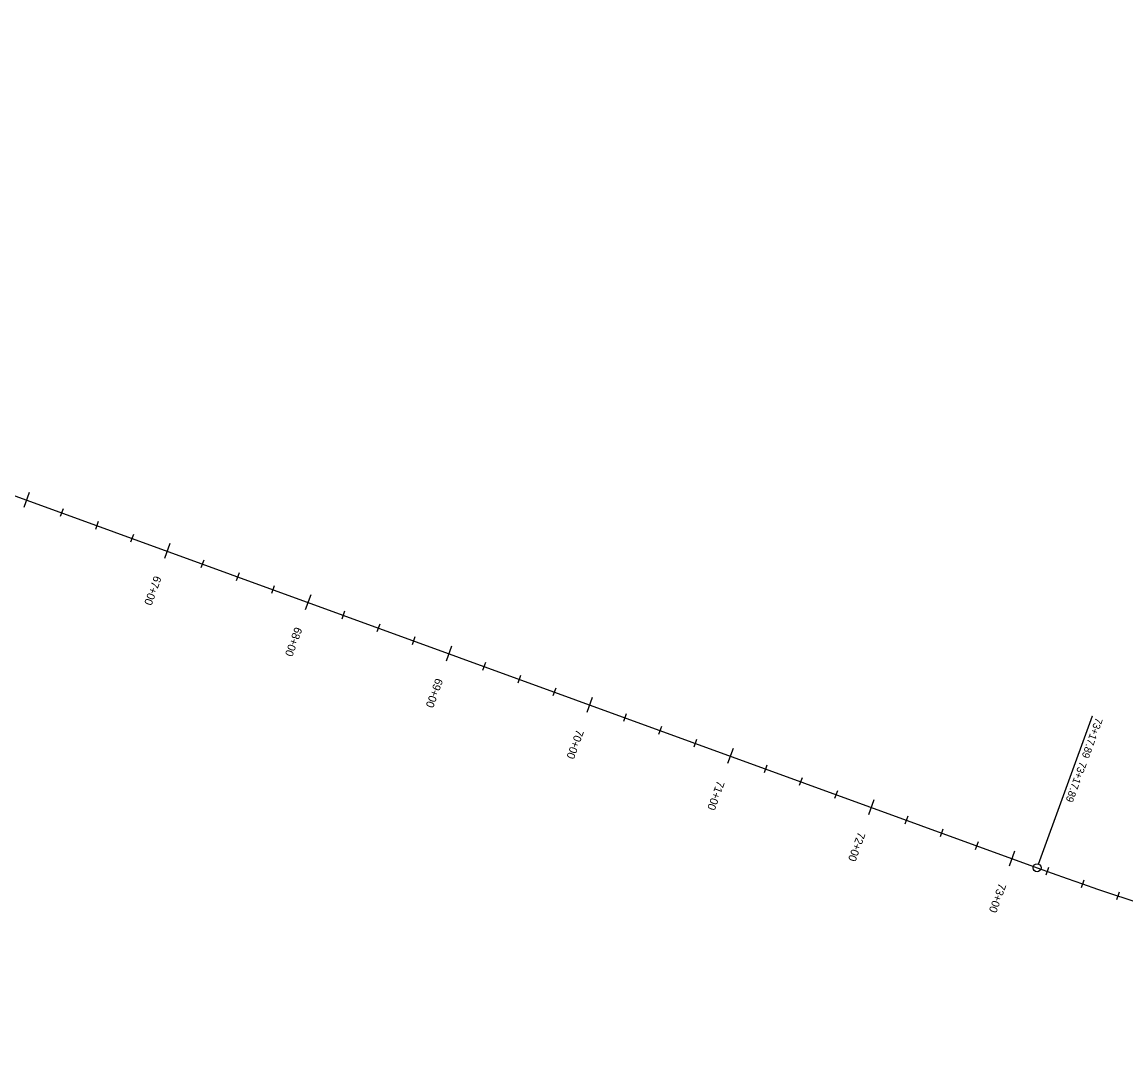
# Model space of a CAD drawing. Extents: x 2301963 to 2307911, y 760768 to 761974.
# Drawn here: x 2303447 to 2304184, y 760898 to 761590 of the extents above; entities that cross this region are included whole.
import ezdxf

# ---------------------------------------------------------------- set-up
doc = ezdxf.new("R2010")
doc.units = 0
for name, color, linetype in [('Default', 7, 'Continuous'), ('Draft_Station Cardinal Lines', 7, 'Continuous'), ('Draft_Station Cardinal Points', 7, 'Continuous'), ('Draft_Station Labels Major', 7, 'Continuous'), ('Draft_Station Ticks Major', 7, 'Continuous'), ('Draft_Station Ticks Minor', 7, 'Continuous'), ('Geom_Secondary', 7, 'Continuous')]:
    doc.layers.add(name, color=color, linetype=linetype)

msp = doc.modelspace()

# ---------------------------------------------------------------- linework, layer by layer
at = {"layer": 'Default'}
msp.add_line((2302574.09, 761590.06), (2304124.97, 761025.72), dxfattribs=at)
msp.add_arc((2304853.32, 763027.32), 2130, 250.00439, 268.36584, dxfattribs=at)
at = {"layer": 'Draft_Station Cardinal Lines'}
msp.add_line((2304125.88, 761028.23), (2304161.9, 761127.21), dxfattribs=at)
at = {"layer": 'Draft_Station Cardinal Points'}
for p, q in [((2304161.9, 761127.21), (2304161.9, 761127.21)), ((2304124.97, 761025.72), (2304124.97, 761025.72))]:
    msp.add_line(p, q, dxfattribs=at)
msp.add_circle((2304124.97, 761025.72), 2.67, dxfattribs=at)
at = {"layer": 'Draft_Station Ticks Major'}
for p, q in [((2303452.18, 761276.22), (2303448.55, 761266.24)), ((2303546.16, 761242.03), (2303542.52, 761232.05)), ((2303640.13, 761207.83), (2303636.5, 761197.85)), ((2303734.1, 761173.64), (2303730.47, 761163.66)), ((2303828.07, 761139.44), (2303824.44, 761129.46)), ((2303922.04, 761105.25), (2303918.41, 761095.27)), ((2304016.01, 761071.05), (2304012.38, 761061.07)), ((2304109.99, 761036.86), (2304106.36, 761026.88))]:
    msp.add_line(p, q, dxfattribs=at)
at = {"layer": 'Draft_Station Ticks Minor'}
for p, q in [((2303474.79, 761265.25), (2303472.91, 761260.06)), ((2303498.29, 761256.7), (2303496.4, 761251.51)), ((2303521.78, 761248.15), (2303519.89, 761242.96)), ((2303568.77, 761231.05), (2303566.88, 761225.87)), ((2303592.26, 761222.51), (2303590.37, 761217.32)), ((2303615.75, 761213.96), (2303613.86, 761208.77)), ((2303662.74, 761196.86), (2303660.85, 761191.67)), ((2303686.23, 761188.31), (2303684.34, 761183.12)), ((2303709.72, 761179.76), (2303707.84, 761174.57)), ((2303756.71, 761162.66), (2303754.82, 761157.48)), ((2303780.2, 761154.12), (2303778.32, 761148.93)), ((2303803.7, 761145.57), (2303801.81, 761140.38)), ((2303850.68, 761128.47), (2303848.79, 761123.28)), ((2303874.17, 761119.92), (2303872.29, 761114.73)), ((2303897.67, 761111.37), (2303895.78, 761106.18)), ((2303944.65, 761094.27), (2303942.77, 761089.09)), ((2303968.15, 761085.73), (2303966.26, 761080.54)), ((2303991.64, 761077.18), (2303989.75, 761071.99)), ((2304038.63, 761060.08), (2304036.74, 761054.89)), ((2304062.12, 761051.53), (2304060.23, 761046.34)), ((2304085.61, 761042.98), (2304083.72, 761037.8)), ((2304132.59, 761025.9), (2304130.72, 761020.71)), ((2304156.13, 761017.58), (2304154.32, 761012.36)), ((2304179.77, 761009.53), (2304178.02, 761004.3))]:
    msp.add_line(p, q, dxfattribs=at)
at = {"layer": 'Geom_Secondary'}
msp.add_line((2302574.09, 761590.06), (2304124.97, 761025.72), dxfattribs=at)
msp.add_arc((2304853.32, 763027.32), 2130, 250.00439, 268.36584, dxfattribs=at)

# ---------------------------------------------------------------- texts
at = {"layer": 'Draft_Station Cardinal Points'}
for p in [(2304164.24, 761126.36), (2304153.55, 761096.99)]:
    msp.add_text('73+17.89', height=5, rotation=250.00439, dxfattribs=at).set_placement(p)
at = {"layer": 'Draft_Station Labels Major'}
for s, p in [('67+00', (2303535.67, 761221.01)), ('68+00', (2303629.64, 761186.81)), ('69+00', (2303723.61, 761152.62)), ('70+00', (2303817.58, 761118.42)), ('71+00', (2303911.55, 761084.23)), ('72+00', (2304005.52, 761050.03)), ('73+00', (2304099.5, 761015.84))]:
    msp.add_text(s, height=5.34, rotation=250.00439, dxfattribs=at).set_placement(p)

doc.saveas('drawing.dxf')
